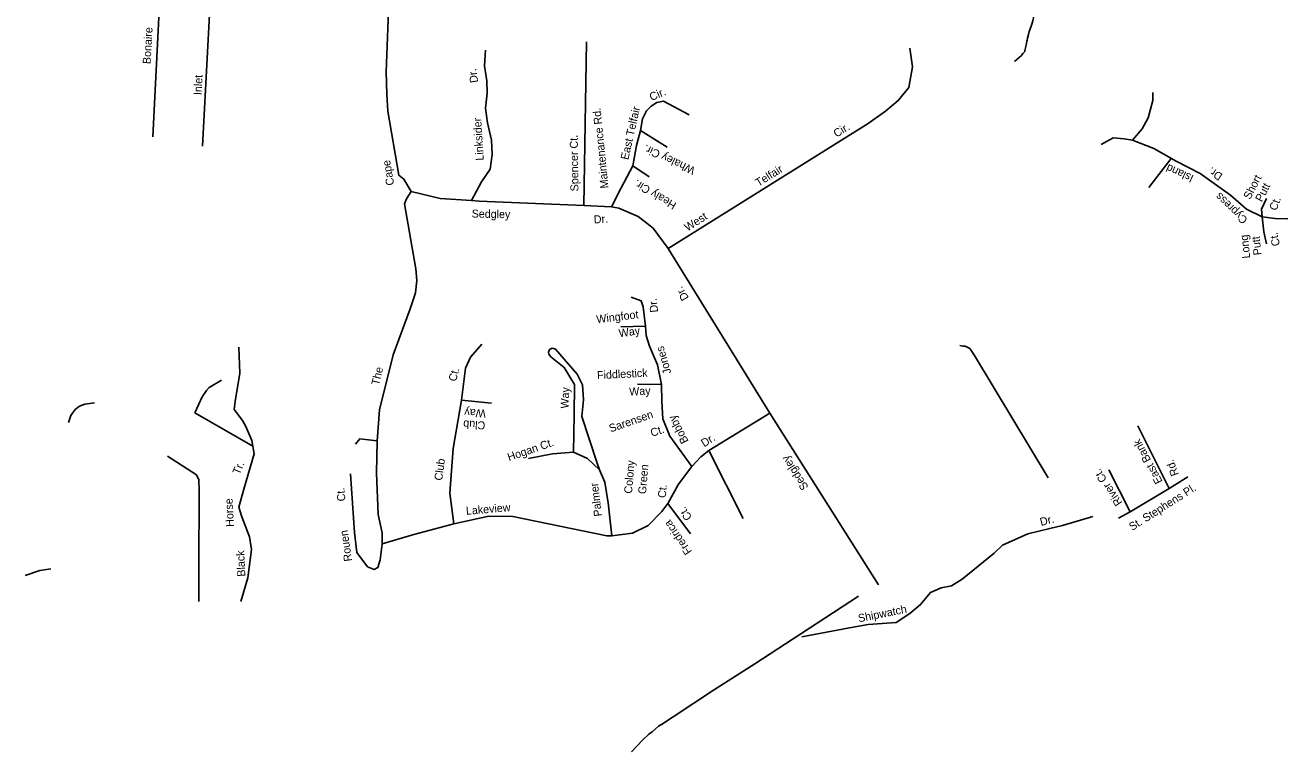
# Model space of a CAD drawing. Extents: x 2308163 to 2335412, y -96774 to 125428.
# Drawn here: x 2322445 to 2327622, y -51162 to -48182 of the extents above; entities that cross this region are included whole.
import ezdxf

# ---------------------------------------------------------------- set-up
doc = ezdxf.new("R2010")
doc.units = 0
doc.layers.add('Old_Level_10', color=7, linetype='Continuous')
doc.layers.add('Old_Level_35', color=7, linetype='Continuous')

msp = doc.modelspace()

# ---------------------------------------------------------------- linework, layer by layer
at = {"layer": 'Old_Level_35'}
for points in [[(2323172.5, -48678.1), (2323205.7, -48034.1), (2323224.4, -47811.2), (2323225, -47580.3), (2323244.2, -47342.7), (2323226.4, -47114.8), (2323227.9, -46964.5), (2323265.3, -46837.5), (2323280.2, -46724.4), (2323282.3, -46559.5)], [(2322968.4, -48639.6), (2323062.6, -46760.9), (2323042.6, -46595.3)], [(2324027.8, -48864.3), (2323998.2, -48813), (2323977.7, -48797.6), (2323932.3, -48534.3), (2323928.4, -48465), (2323925.3, -48372.8), (2323932.7, -48159.4), (2323930.4, -48104.8), (2323922.4, -47970.5), (2323913.8, -47857.1), (2323917.9, -47796.5), (2323941, -47736.6), (2323989.3, -47673.3), (2324024.9, -47611.7), (2324057.2, -47527), (2324096, -47373.3), (2324135, -47215.5), (2324188.1, -47012.1), (2324232.6, -46816.7), (2324247.7, -46706.5)], [(2326553.3, -48244), (2326555.7, -48235.6), (2326559.1, -48220.6), (2326562.3, -48207.6), (2326568.8, -48189.9), (2326574.3, -48173), (2326577.5, -48163.9), (2326578.6, -48157.1), (2326579.7, -48151.1), (2326578.9, -48142.1), (2326580.1, -48132.1), (2326576.2, -48092.9), (2326569.8, -48026.7), (2326561.5, -47952.5), (2326558.1, -47927.4), (2326558, -47894.5), (2326556.9, -47855.4), (2326559.4, -47790.5), (2326562.8, -47688.5), (2326569.3, -47543.6), (2326573.2, -47441.5)], [(2324735.6, -48921), (2324746.5, -48249.9)], [(2326501.4, -48330.3), (2326530, -48306), (2326536.2, -48298.1), (2326541.2, -48292.2), (2326544.3, -48289.4), (2326544.5, -48285.3), (2326549.1, -48263.5), (2326552.3, -48247.5), (2326553.3, -48244)], [(2324332.5, -48284.2), (2324328.1, -48348.9), (2324338.6, -48410), (2324339, -48460.3), (2324332.6, -48522.9), (2324341.1, -48581.9), (2324357.4, -48653.6), (2324359.6, -48712.4), (2324351.2, -48772.8), (2324315.9, -48824), (2324275.6, -48900.9)], [(2325081.5, -49098.3), (2325902, -48585), (2325972.9, -48535.1), (2326024.7, -48490.8), (2326068.5, -48437.9), (2326084, -48352.5), (2326071.9, -48276.7)], [(2326985.2, -48652.9), (2327025, -48607.6), (2327050, -48561.7), (2327069.4, -48490.3), (2327068.4, -48458.4)], [(2324848.5, -48926.9), (2324886.8, -48851.6), (2324936.1, -48759.1), (2324951.5, -48675.8), (2324968.3, -48613.6), (2324976.3, -48565.7), (2324992.1, -48532.7), (2325011.6, -48514.5), (2325035.2, -48498.6), (2325062.6, -48493.2), (2325167.6, -48549.2)], [(2324968.3, -48613.6), (2325077, -48682.2)], [(2326857.2, -48671.8), (2326907, -48643.8), (2326951.4, -48647.5), (2326985.2, -48652.9), (2327073.2, -48687.7), (2327164.8, -48739.7), (2327262.9, -48789.7), (2327387.2, -48878.9), (2327453.2, -48936.3), (2327517.9, -48968.3), (2327514.8, -48936.3), (2327535.4, -48892.5)], [(2324936.1, -48759.1), (2325003.7, -48803.3)], [(2327052.8, -48848.3), (2327144.9, -48728.4)], [(2324027.8, -48864.3), (2324007.9, -48894.6), (2324000.9, -48915.3), (2324046.3, -49180.8), (2324050.9, -49229.1), (2324045, -49279.2), (2324023.8, -49345.5), (2323954.4, -49533.7), (2323898.4, -49759.6), (2323887.8, -49887), (2323885.3, -50018.9), (2323892, -50188.7), (2323908.3, -50264.7), (2323908.9, -50308.7), (2323900.3, -50375.4), (2323890.8, -50406.5), (2323875.9, -50414.4), (2323849, -50403), (2323804.9, -50344.9), (2323795.2, -50262.9), (2323778.3, -50021.5)], [(2325178.6, -49992.7), (2325215.6, -49952.1), (2325247.9, -49925.9), (2325498.4, -49773.3), (2325081.5, -49098.3), (2325019.5, -49014.5), (2324958.3, -48966.3), (2324879.8, -48932.2), (2324848.5, -48926.9), (2324735.6, -48921), (2324306.9, -48904.1), (2324275.6, -48900.9), (2324145.9, -48892.2), (2324027.8, -48864.3)], [(2327517.9, -48968.3), (2327524.3, -49030), (2327535.3, -49079.2)], [(2327517.9, -48968.3), (2327570.8, -48974.3), (2327622.3, -48976.5)], [(2323908.9, -50308.7), (2324038, -50271.3), (2324203, -50226.7), (2324346.6, -50196), (2324445.1, -50197.3), (2324730.2, -50255.8), (2324830.1, -50276), (2324851, -50276.7), (2324935.3, -50264.9), (2324999.2, -50233.6), (2325055.7, -50176.9), (2325079.9, -50144.3), (2325123.7, -50064.1), (2325178.6, -49992.7), (2325088.5, -49868.1), (2325059.6, -49795.9), (2325055.8, -49724.5), (2325054, -49655.4), (2325037.9, -49575.2), (2325004.9, -49498.7), (2324991.7, -49454.2), (2324988.8, -49416.4), (2324979, -49336.5), (2324971.4, -49313.2), (2324930.1, -49297.1)], [(2324988.8, -49416.4), (2324888.1, -49419.2)], [(2324203, -50226.7), (2324186.8, -50101.7), (2324199.4, -49917.8), (2324233.5, -49720), (2324250.6, -49588.7), (2324271, -49543.3), (2324316.8, -49490.4)], [(2323329.1, -50546.2), (2323358.3, -50449.2), (2323373.3, -50332.4), (2323364.1, -50280.8), (2323333.9, -50199.1), (2323320.6, -50158.3), (2323341.5, -50085.7), (2323383.2, -49940.5), (2323374.1, -49885.2), (2323349.5, -49827.6), (2323336.6, -49803.3), (2323301.4, -49758.1), (2323306.2, -49725.2), (2323324.9, -49608.6), (2323321.3, -49502.2)], [(2324693.5, -49932.8), (2324696.7, -49780), (2324696.8, -49656.4), (2324655.2, -49585.9), (2324600.1, -49542.1), (2324592.1, -49531.4), (2324590.3, -49522.9), (2324594.8, -49512.6), (2324605.5, -49506.7), (2324620, -49511.4), (2324708.8, -49612.9), (2324730.3, -49657.6), (2324734.5, -49718.5), (2324727.9, -49787.4), (2324788.5, -49973.8), (2324800, -50005.6)], [(2326639.3, -50038.4), (2326490.2, -49790.7), (2326337.2, -49537), (2326318.9, -49507.4), (2326311, -49503.3), (2326300.1, -49499.1), (2326290.1, -49497.9), (2326277.2, -49495.5)], [(2323140.5, -49771.4), (2323170.9, -49706.8), (2323188.6, -49680.7), (2323199, -49667.7), (2323249.5, -49638)], [(2325054, -49655.4), (2324955.5, -49654.1)], [(2322622.9, -49812), (2322632.2, -49783.1), (2322650, -49758.3), (2322668, -49745.1), (2322689.7, -49735.8), (2322728.8, -49730.9)], [(2324233.5, -49720), (2324356.7, -49732.7)], [(2323140.5, -49771.4), (2323377.9, -49908.4)], [(2325498.4, -49773.3), (2325943.5, -50477.2)], [(2327007.2, -49825.3), (2327136.4, -50082.2), (2327212.4, -50033.9)], [(2323887.8, -49887), (2323816.8, -49878.3), (2323799.3, -49900.7)], [(2323028.1, -49949.3), (2323147.3, -50025.8), (2323156.7, -50046.6), (2323158.5, -50090.9), (2323157.5, -50410.7), (2323157.4, -50545.7)], [(2324851, -50276.7), (2324835.2, -50140.8), (2324821.3, -50056.6), (2324800, -50005.6), (2324751.3, -49959.9), (2324693.5, -49932.8), (2324607.3, -49940.3), (2324508.2, -49959.9)], [(2325247.9, -49925.9), (2325389.2, -50205.2)], [(2326975.9, -50178.5), (2326888.5, -50005.8)], [(2327136.4, -50082.2), (2326975.9, -50178.5), (2326928.3, -50204.5)], [(2325079.9, -50144.3), (2325173.2, -50268.9)], [(2325630, -50690.1), (2325824.8, -50654.4), (2325901.8, -50640.1), (2326016.7, -50631.3), (2326073.2, -50595.1), (2326116.9, -50558.4), (2326156.8, -50508.9), (2326200.8, -50489.2), (2326243.5, -50482.1), (2326287, -50453.9), (2326418, -50348.1), (2326453.1, -50315.4), (2326556.7, -50268), (2326646.6, -50245.7), (2326698, -50234.7), (2326822.4, -50196.6)], [(2322445.1, -50439), (2322504.3, -50418.3), (2322550.1, -50412.3)], [(2325862.6, -50524.1), (2325625.8, -50678.7), (2325436.7, -50801.2), (2325268, -50910.1), (2325102.3, -51019.1), (2325053.6, -51051), (2325042.3, -51057.8), (2325015.8, -51080.1), (2325002.4, -51089.8), (2324975.8, -51115.2), (2324931.3, -51162.1)]]:
    msp.add_lwpolyline(points, dxfattribs=at)

# ---------------------------------------------------------------- texts
at = {"layer": 'Old_Level_10'}
for s, height, rotation, p in [('Bonaire', 32.81, 86.8529, (2322959, -48342.1)), ('Inlet', 32.81, 87.8162, (2323168.9, -48469.1)), ('Dr.', 32.81, 98.3115, (2324302.4, -48415.9)), ('Cir.', 32.81, 22.8854, (2325013, -48493.3)), ('Maintenance Rd.', 32.808, 95.7048, (2324837.1, -48849.8)), ('East Telfair ', 32.808, 77.2768, (2324917.9, -48736.2)), ('Linksider', 32.81, 93.4684, (2324325.3, -48736.3)), ('Cir.', 32.81, 31.7692, (2325772, -48643.5)), ('Spencer Ct.', 32.808, 90.7324, (2324713.6, -48863.3)), ('Whaley Cir.', 32.808, 154.835, (2325195.4, -48766.9)), ('Cape', 32.81, 99.9628, (2323958.6, -48836.4)), ('Telfair', 32.81, 31.8069, (2325451.9, -48845)), (' Island ', 32.81, 155.2034, (2327250.4, -48804.1)), ('Dr.', 32.81, 146.8638, (2327358, -48794.1)), ('Healy Cir.', 32.81, 149.1209, (2325118.5, -48912)), ('Short', 32.81, 62.5056, (2327467.5, -48899.4)), ('Cypress', 32.81, 136.1992, (2327460.6, -48977.4)), ('Putt', 32.81, 62.5056, (2327516, -48909.3)), ('Ct.', 32.81, 68.6681, (2327575.2, -48945.2)), ('Sedgley', 32.81, 358.9794, (2324275.5, -48970.9)), ('Dr.', 32.81, 3.7721, (2324777.5, -48995.4)), ('West', 32.81, 32.3643, (2325160.7, -49028.4)), ('Long', 32.81, 95.9768, (2327468.6, -49137.1)), ('Putt', 32.81, 95.9768, (2327515, -49123.8)), ('Ct.', 32.81, 101.7692, (2327590.7, -49084.6)), ('Dr.', 32.81, 121.0201, (2325167.5, -49300)), ('Dr.', 32.81, 96.5311, (2325040.6, -49358.6)), ('Wingfoot ', 32.81, 6.8876, (2324789.1, -49404.4)), ('Way', 32.81, 8.3091, (2324881.4, -49462.2)), ('Jones', 32.81, 106.3222, (2325094.6, -49607.8)), ('The ', 32.81, 76.327, (2323895.6, -49661.3)), ('Ct.', 32.81, 75.0685, (2324211.4, -49645.6)), ('Fiddlestick', 32.808, 2.8383, (2324790.7, -49633.9)), ('Way', 32.81, 87.7119, (2324672.9, -49754.9)), ('Way', 32.81, 2.8383, (2324922.5, -49701.3)), ('Way', 32.81, 176.6967, (2324334.5, -49759.1)), ('Club', 32.81, 176.6967, (2324332.4, -49807.9)), ('Sarensen', 32.81, 19.2289, (2324845.6, -49852.7)), ('Bobby', 32.81, 117.1145, (2325166, -49888.4)), ('Ct.', 32.81, 19.2289, (2325015.5, -49871)), ('Hogan Ct.', 32.81, 19.0033, (2324429, -49970.5)), ('Dr.', 32.81, 32.3018, (2325229.2, -49913.7)), ('East Bank', 32.81, 118.3259, (2327110, -50053.2)), ('Sedgley', 32.81, 122.9112, (2325658.3, -50076.2)), ('Tr.', 32.81, 66.8835, (2323323.6, -50028.1)), ('Club ', 32.81, 82.3139, (2324154.5, -50051.3)), ('Colony', 32.81, 85.3278, (2324933.1, -50104.3)), ('Green ', 32.81, 85.3278, (2324990.6, -50106.2)), ('River Ct.', 32.81, 123.4059, (2326945.6, -50140.6)), ('Rd.', 32.81, 110.7645, (2327176.2, -50024.1)), ('Palmer', 32.81, 97.0173, (2324810.4, -50195)), ('Ct.', 32.81, 94.6733, (2323758.2, -50133.8)), ('Ct.', 32.81, 85.3278, (2325071.6, -50122.1)), ('St. Stephens Pl.', 32.808, 32.4762, (2326984.3, -50256.8)), ('Horse', 32.81, 92.966, (2323301.2, -50238.9)), ('Lakeview', 32.81, 4.7502, (2324253.6, -50190.4)), ('Ct.', 32.81, 124.4823, (2325181.3, -50200.2)), ('Fredrica', 32.81, 124.4823, (2325180.5, -50340.5)), ('Dr.', 32.81, 14.4843, (2326610.7, -50236.1)), ('Rouen', 32.81, 98.3217, (2323785.4, -50379.2)), ('Black', 32.81, 92.67, (2323347.8, -50443.2)), ('Shipwatch', 32.81, 11.3903, (2325863.8, -50631.4))]:
    msp.add_text(s, height=height, rotation=rotation, dxfattribs=at).set_placement(p)

doc.saveas('drawing.dxf')
